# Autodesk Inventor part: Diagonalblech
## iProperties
Shininess: 64.0
Length Units: 11269
Angle Units: 11279
Time Units: 11290
Mass Units: 11283
Length Display Precision: 3
Angle Display Precision: 2
Compacted: True
Part Number: Diagonalblech
Document SubType Name: Modeling
Created: 2004-10
Material: Standard
Cost Center: 0,3 kg
Designer: thomas
Manufacturer: Standard
Standards Organization: Custom
Density: 0.0
Volumn: 0.0
Area: 0.0
PropertySet Name: Model Information
Control State: 0
Master: False
Checked Out: False
SaveDate: 2004-10-15
SaveTime: 17:11
TotalMass: 0,3 kg
Author: thomas
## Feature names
1. Extrusion1
2. Trennen1
3. Trennen2
4. Rundung1 [Fillet]
